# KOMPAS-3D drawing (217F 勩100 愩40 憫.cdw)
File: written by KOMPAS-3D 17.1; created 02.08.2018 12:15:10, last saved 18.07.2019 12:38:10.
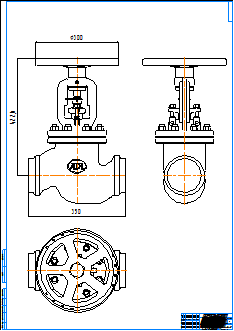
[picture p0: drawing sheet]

Sheet 1: A0, portrait

Title block, sheet 1: name: 217F Ду100 Ру40 СС; material: Внимание! Данный продукт является объектом авторского права ООО «Торговый Дом АДЛ». / Запрещается изменение, копирование, распространение / (в том числе путем копирования на другие сайты и ресурсы в Интернете) / или любое иное использование информации и объектов без предварительного / согласия правообладателя (ООО «Торговый Дом АДЛ»).; sheets: 1; organisation: ООО "Торговый дом АДЛ"; sheet format: A0; stored path: \\adlc.lan\data\АДЛ_ПКД\3D-модели\Поставщики\Zetkama\Вентили\217F\KOMPAS 2D\217F Ду100 Ру40 СС.cdw

Views: Вид 1, Проекционный вид 2, Проекционный вид 3
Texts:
  kka
  adl
Dimensions and other numbers on the sheet: 350; 422,6; 300; 1:1; 1; 217F Ду100 Ру40 СС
